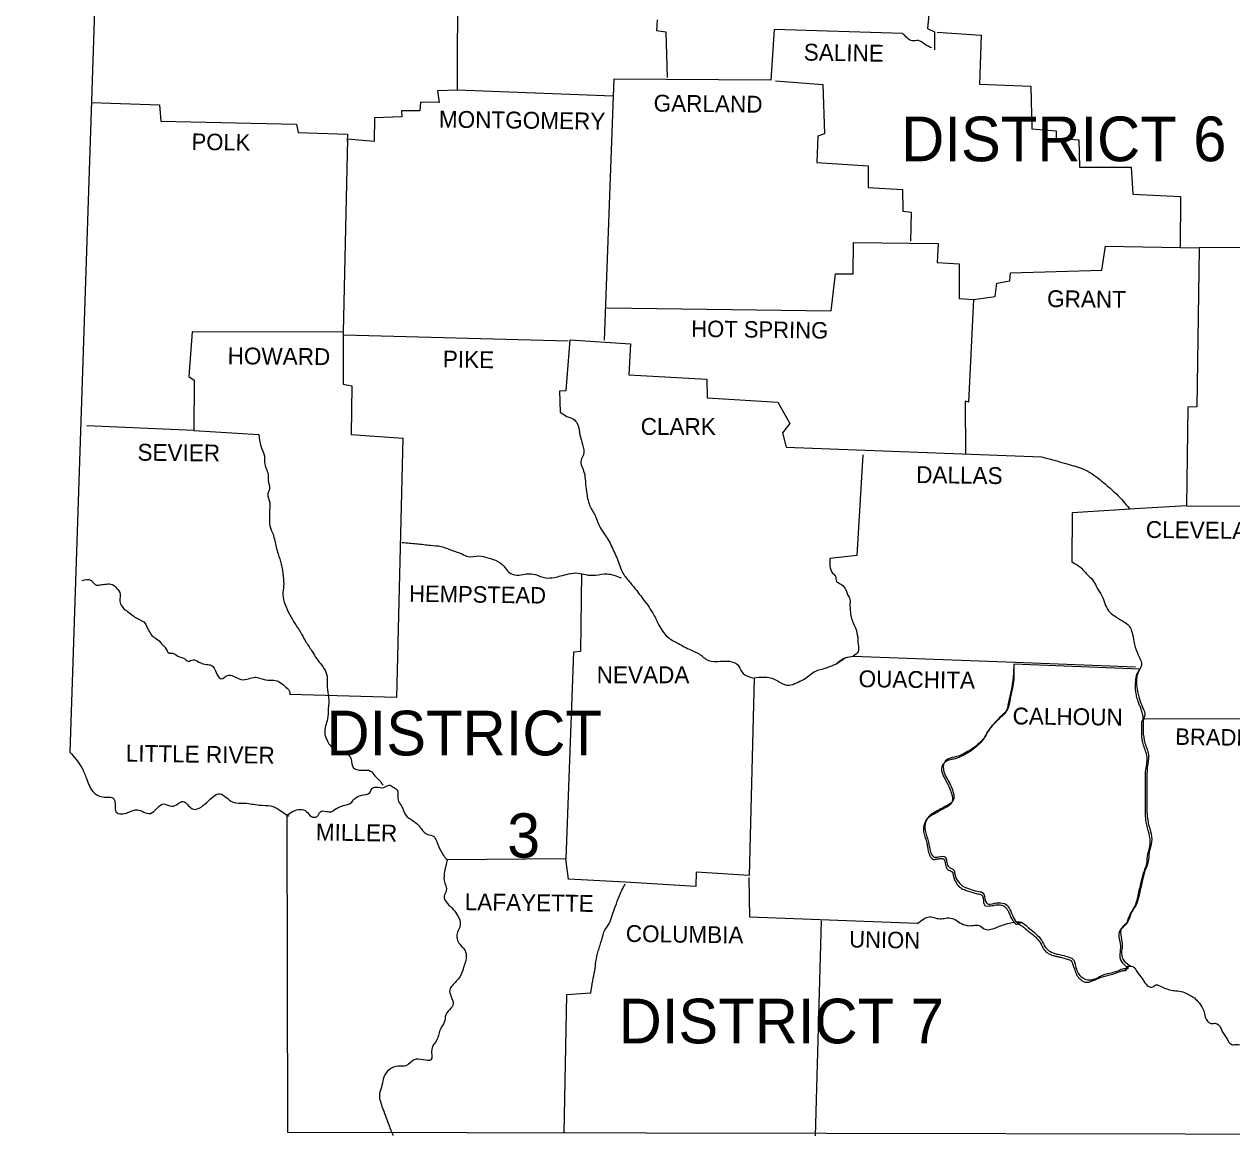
# Model space of a CAD drawing. Extents: x 172 to 3385, y 73 to 2074.
# Drawn here: x 2703.7 to 3005.2, y 1432.6 to 1710.1 of the extents above; entities that cross this region are included whole.
import ezdxf

# ---------------------------------------------------------------- set-up
doc = ezdxf.new("R2010")
doc.units = 0
for name, color, linetype in [('R_Border', 7, 'Continuous'), ('R_Border Prem', 7, 'Continuous'), ('R_Grid', 7, 'Continuous'), ('S_MISC_BOUNDARY', 7, 'Continuous')]:
    doc.layers.add(name, color=color, linetype=linetype)

msp = doc.modelspace()

# ---------------------------------------------------------------- linework, layer by layer
at = {"layer": 'R_Border Prem'}
for points in [[(2703.71, 1956.42), (2723.96, 1793.81), (2715.15, 1528.37)], [(2812.02, 1750.86), (2811.82, 1693.62), (2806.93, 1693.52), (2807.32, 1690.59), (2802.62, 1690.68), (2802.53, 1688.53), (2797.93, 1688.53), (2798.03, 1686.97), (2791.18, 1686.77), (2791.08, 1680.8), (2784.43, 1681.39), (2783.35, 1633.25), (2745.68, 1633.35), (2744.8, 1622.19), (2746.17, 1621.22), (2746.07, 1608.69), (2719.36, 1609.87)], [(2961.91, 1722.77), (2954.86, 1723.56), (2955.16, 1720.92), (2942.34, 1720.43), (2941.95, 1716.61), (2929.91, 1715.93), (2929.23, 1709.08), (2930.99, 1708.2), (2930.99, 1703.7)], [(2861.72, 1711.23), (2861.62, 1708.59), (2863.87, 1708.2), (2864.26, 1696.85)], [(2922.97, 1707.81), (2890.97, 1708.78), (2890.09, 1696.16), (2850.96, 1696.36), (2850.76, 1692.15)], [(2931.68, 1708.1), (2942.63, 1707.41), (2942.24, 1695.18), (2955.06, 1694.69), (2955.26, 1684.03), (2961.32, 1683.54), (2961.32, 1681.68), (2967, 1681.29), (2967.19, 1674.44), (2980.11, 1674.44), (2980.5, 1667.69), (2992.44, 1667.1), (2992.34, 1654.38)], [(2891.27, 1695.97), (2903.11, 1695.09), (2903.5, 1682.76), (2901.83, 1682.17), (2901.64, 1675.62), (2914.46, 1674.74), (2914.46, 1669.35), (2922.97, 1668.86), (2923.07, 1663.48), (2925.12, 1663.19), (2925.02, 1655.95)], [(2850.76, 1692.15), (2811.82, 1693.62)], [(2850.76, 1692.15), (2848.51, 1631.2)], [(2720.54, 1690.59), (2737.46, 1690), (2737.85, 1685.89), (2771.71, 1685.2), (2772.1, 1683.05), (2784.43, 1682.66), (2784.33, 1680.8)], [(3109.06, 1665.64), (3072.08, 1666.61), (3071.88, 1654.58), (2997.03, 1654.29)], [(2849.2, 1639.32), (2905.16, 1638.53), (2906.24, 1647.83), (2910.64, 1647.83), (2910.74, 1655.66), (2931.87, 1655.36), (2931.68, 1650.67), (2937.16, 1650.27), (2937.16, 1641.66), (2940.68, 1641.37)], [(2940.68, 1641.37), (2946.16, 1642.15), (2946.55, 1645.48), (2949.78, 1646.07), (2949.97, 1648.02), (2972.77, 1648.71), (2973.65, 1654.68), (2997.03, 1654.29)], [(2997.03, 1654.09), (2996.45, 1614.56), (2994.2, 1614.47), (2993.9, 1589.91)], [(2940.68, 1641.37), (2939.5, 1615.74), (2938.62, 1616.03), (2938.72, 1602.72)], [(2783.35, 1633.25), (2783.35, 1620.24), (2785.5, 1619.85), (2785.31, 1607.71), (2798.22, 1606.74), (2796.66, 1542.06), (2770.04, 1542.75)], [(2783.55, 1632.57), (2839.51, 1631.1)], [(2837.65, 1613.19), (2837.46, 1618.57), (2839.02, 1618.67), (2840, 1631.29), (2855.07, 1630.32), (2854.68, 1622.59), (2874.15, 1621.51), (2874.24, 1616.81), (2891.85, 1615.74), (2894.89, 1610.45), (2893.03, 1608.11), (2893.91, 1604.49), (2957.7, 1602.14)], [(2746.07, 1608.69), (2762.31, 1607.71)], [(2913.09, 1602.63), (2911.62, 1577.48), (2904.87, 1576.7)], [(2979.81, 1589.03), (2965.33, 1588.15), (2965.24, 1575.92)], [(2993.9, 1589.91), (2979.62, 1589.03)], [(2993.9, 1589.91), (3028.54, 1589.71)], [(2842.84, 1572.98), (2842.64, 1553.51), (2840.88, 1553.31), (2838.92, 1501.75)], [(2910.64, 1552.34), (2951.15, 1550.87), (2981.18, 1549.69)], [(2885.98, 1546.86), (2884.71, 1497.55), (2871.5, 1498.43), (2871.41, 1494.81), (2853.79, 1495.88)], [(2983.14, 1536.68), (3027.36, 1536.78)], [(2769.26, 1512.61), (2769.46, 1433.46), (3128.04, 1432.87)], [(2853.79, 1495.88), (2839.61, 1496.67), (2838.92, 1501.75), (2809.28, 1501.46)], [(2926.69, 1485.61), (2884.91, 1487.17), (2884.71, 1497.06)], [(2902.72, 1486.29), (2901.15, 1432.58)], [(2845.18, 1468.19), (2839.12, 1467.8), (2838.43, 1433.36)]]:
    msp.add_lwpolyline(points, dxfattribs=at)
for points in [[(2930.31, 1704.19), (2928.45, 1705.16), (2926.98, 1706.04), (2925.41, 1705.95), (2924.14, 1706.73), (2922.97, 1707.81)], [(2837.65, 1613.19), (2839.22, 1612.21), (2841.08, 1611.33), (2842.05, 1609.87), (2842.45, 1607.62), (2843.13, 1605.17), (2843.33, 1602.63), (2842.74, 1601.26), (2843.52, 1598.13), (2843.82, 1595.97), (2844.11, 1593.43), (2844.89, 1590.01), (2846.16, 1587.66), (2847.34, 1584.82), (2849.29, 1581.79), (2850.96, 1578.46), (2851.74, 1576.7), (2853.21, 1573.08), (2855.07, 1570.63), (2858, 1566.91), (2860.64, 1563.1), (2862.11, 1560.26), (2864.36, 1557.13), (2866.91, 1555.57), (2870.13, 1553.9), (2872.19, 1552.92), (2874.54, 1551.26), (2877.57, 1551.06), (2879.82, 1551.06), (2881.88, 1550.18), (2882.85, 1548.42), (2884.61, 1547.25), (2885.98, 1546.86)], [(2762.31, 1607.71), (2762.8, 1604.78), (2763.68, 1602.24), (2763.78, 1600.28), (2764.66, 1597.34), (2764.66, 1596.27), (2764.96, 1594.11), (2764.56, 1592.94), (2765.05, 1590.59), (2764.96, 1588.83), (2764.96, 1587.36), (2765.05, 1584.92), (2765.84, 1582.76), (2766.62, 1579.54), (2767.11, 1577.87), (2767.89, 1575.33), (2768.38, 1572.2), (2768.48, 1569.85), (2768.28, 1567.7), (2768.87, 1565.25), (2769.95, 1562.81), (2771.32, 1560.46), (2772.98, 1557.82), (2774.15, 1555.76), (2775.62, 1553.51), (2776.79, 1551.65), (2778.56, 1549.3), (2779.34, 1547.35), (2779.34, 1544.61), (2779.73, 1542.06), (2779.63, 1539.23), (2779.44, 1536.68), (2778.75, 1533.16), (2779.24, 1531.5), (2781.1, 1529.05), (2782.27, 1528.37), (2784.33, 1527.97), (2785.31, 1526.6), (2785.89, 1524.55), (2787.95, 1523.86), (2790.2, 1523.67), (2791.27, 1522.49), (2792.74, 1520.93), (2793.23, 1520.15)], [(2957.7, 1602.14), (2965.33, 1599.98), (2969.25, 1598.52), (2973.16, 1595.68), (2976.39, 1592.84), (2979.62, 1589.22)], [(2798.03, 1580.71), (2801.74, 1580.42), (2805.17, 1580.03), (2807.81, 1579.73), (2810.55, 1578.75), (2813, 1577.87), (2814.56, 1577.19), (2817.2, 1577.38), (2819.45, 1576.89), (2822, 1576.01), (2823.86, 1574.35), (2825.03, 1573.08), (2827.28, 1572.59), (2829.14, 1572.88), (2831.39, 1572.69), (2833.93, 1571.9), (2835.99, 1572), (2837.65, 1572.39), (2839.61, 1572.88), (2842.05, 1573.08), (2843.91, 1572.69), (2846.36, 1572.59), (2849.2, 1572.88), (2852.72, 1571.9)], [(2904.87, 1576.7), (2904.87, 1574.84), (2905.55, 1573.08), (2906.24, 1572.3), (2906.53, 1571.02), (2907.41, 1570.44), (2908.68, 1569.26), (2909.37, 1567.6), (2909.86, 1566.52), (2909.86, 1565.15), (2909.96, 1563.78), (2910.15, 1562.12), (2911.33, 1559.19), (2911.62, 1558.01), (2911.81, 1557.03), (2911.91, 1555.37), (2911.91, 1553.41), (2910.64, 1552.34)], [(2965.24, 1575.92), (2967.49, 1574.45), (2969.34, 1572.49), (2970.71, 1571.02), (2971.59, 1569.36), (2972.77, 1567.4), (2974.43, 1563.69), (2975.9, 1562.41), (2977.95, 1561.14), (2979.23, 1560.26), (2980.5, 1557.42), (2981.09, 1554.59), (2982.16, 1552.04), (2982.65, 1550.09), (2981.77, 1548.13), (2981.57, 1544.22), (2982.16, 1541.57), (2982.94, 1539.62), (2983.43, 1537.37), (2983.14, 1536.68)], [(2718.19, 1571.22), (2720.34, 1571.32), (2721.81, 1570.05), (2722.69, 1570.14), (2724.25, 1570.34), (2725.72, 1570.24), (2726.8, 1569.36), (2727.68, 1567.8), (2727.58, 1566.33), (2727.68, 1565.74), (2728.36, 1564.47), (2729.54, 1563.49), (2730.81, 1562.51), (2731.98, 1561.73), (2733.94, 1560.46), (2734.14, 1560.07), (2734.92, 1558.5), (2735.9, 1557.23), (2737.07, 1556.45), (2738.34, 1555.08), (2738.93, 1554.49), (2739.91, 1553.12), (2740.98, 1553.02), (2742.45, 1552.14), (2743.53, 1551.85), (2744.7, 1551.06), (2745.88, 1551.46), (2747.34, 1550.87), (2749.3, 1550.28), (2750.38, 1550.09), (2751.65, 1548.23), (2752.92, 1546.66), (2754.49, 1547.54), (2757.42, 1546.66), (2759.28, 1546.56), (2760.94, 1547.05), (2762.22, 1546.96), (2764.56, 1546.37), (2766.03, 1546.37), (2767.6, 1545.78), (2769.06, 1544.61), (2770.04, 1543.34), (2770.04, 1542.75)], [(2908.78, 1551.95), (2906.24, 1550.28), (2904.28, 1549.5), (2902.81, 1549.01), (2901.44, 1548.62), (2899.68, 1547.44), (2898.31, 1546.47), (2896.45, 1545.59), (2894.69, 1545), (2892.54, 1545.68), (2891.37, 1546.37), (2890.09, 1546.86), (2885.98, 1546.86)], [(2906.24, 1550.28), (2908.78, 1551.95), (2910.64, 1552.34)], [(2950.75, 1549.69), (2950.56, 1544.8), (2949.87, 1541.77), (2949.19, 1539.03), (2947.72, 1537.46), (2946.16, 1535.9), (2944.69, 1534.14), (2943.42, 1531.99), (2942.14, 1530.62), (2940.48, 1529.25), (2938.82, 1528.27), (2936.96, 1527.39), (2934.9, 1526.9), (2933.44, 1525.82), (2933.34, 1523.47), (2935, 1520.15), (2935.59, 1518.58), (2935.79, 1516.72), (2935.1, 1515.65), (2933.53, 1514.77), (2931.68, 1513.69), (2930.01, 1512.71), (2928.84, 1511.05), (2928.64, 1508.8), (2929.43, 1506.16), (2929.72, 1504.59), (2930.99, 1502.14), (2931.97, 1502.24), (2933.73, 1502.14), (2933.93, 1501.65), (2934.02, 1501.17), (2934.42, 1499.89), (2935.88, 1498.82), (2936.08, 1497.84), (2936.96, 1495.98), (2938.43, 1494.71), (2939.5, 1494.32), (2941.75, 1493.63), (2942.93, 1493.34), (2944.2, 1490.5), (2945.77, 1490.6), (2946.94, 1490.79), (2948.9, 1490.31), (2949.78, 1489.13), (2950.66, 1487.17), (2951.83, 1485.8), (2952.61, 1485.8)], [(2983.14, 1536.68), (2983.53, 1530.62), (2984.41, 1527.68), (2984.12, 1524.55), (2984.02, 1521.52), (2984.02, 1518.78), (2984.02, 1516.14), (2984.02, 1513.4), (2984.22, 1511.44), (2984.9, 1508.6), (2985.19, 1505.96), (2984.61, 1503.42), (2984.31, 1501.07), (2983.53, 1498.72), (2982.85, 1496.08), (2982.06, 1492.65), (2981.38, 1490.4), (2980.01, 1488.06), (2979.13, 1485.9), (2977.76, 1484.53), (2977.56, 1482.18), (2977.86, 1480.03), (2977.66, 1478.08), (2978.35, 1476.22), (2980.11, 1474.94)], [(2715.15, 1528.37), (2717.99, 1524.65), (2719.17, 1522.01), (2720.83, 1518.58), (2723.28, 1517.21), (2726.11, 1516.72), (2726.7, 1513.4), (2729.63, 1513.3), (2731.98, 1513.98), (2735.21, 1513.1), (2738.64, 1515.45), (2740.59, 1514.86), (2743.43, 1516.04), (2745.58, 1514.28), (2749.3, 1515.84), (2752.63, 1517.99), (2755.76, 1515.94), (2758.79, 1515.65), (2762.41, 1515.16), (2765.25, 1514.96), (2767.79, 1513.69), (2769.65, 1512.42), (2769.26, 1512.61)], [(2769.26, 1512.61), (2772.68, 1514.08), (2774.15, 1513.59), (2775.42, 1512.32), (2776.89, 1512.32), (2777.67, 1513.49), (2779.14, 1513.59), (2780.32, 1513.49), (2781.59, 1514.28), (2782.66, 1514.77), (2784.13, 1515.25), (2785.21, 1515.65), (2786.19, 1516.72), (2787.95, 1517.6), (2790, 1518.29), (2790.59, 1519.27), (2791.57, 1519.66), (2793.52, 1519.56), (2794.8, 1520.15), (2795.87, 1519.66), (2796.85, 1518.97), (2797.05, 1516.43), (2797.83, 1515.06), (2799, 1512.61), (2800.67, 1511.34), (2802.23, 1510.07), (2802.82, 1509.29), (2804.48, 1507.82), (2805.95, 1507.33), (2806.64, 1506.25), (2807.71, 1503.71), (2809.28, 1501.46)], [(2809.28, 1501.46), (2808.69, 1498.62), (2808.59, 1496.37), (2809.08, 1493.73), (2808.59, 1492.46), (2809.38, 1490.6), (2810.84, 1489.13), (2811.92, 1487.57), (2812.6, 1485.32), (2811.72, 1482.77), (2812.7, 1480.13), (2813.58, 1479.15), (2814.07, 1477.59), (2813.39, 1474.55), (2812.51, 1472.3), (2810.55, 1470.05), (2809.96, 1468.98), (2810.26, 1467.51), (2810.74, 1465.16), (2810.26, 1464.48), (2808.98, 1462.81), (2808.59, 1460.95), (2807.71, 1459.39), (2806.73, 1456.55), (2805.46, 1454.2), (2805.27, 1451.56), (2803.31, 1451.56), (2801.06, 1451.56), (2799, 1450.09), (2797.15, 1450), (2794.89, 1449.11), (2793.52, 1447.26), (2793.04, 1445.2), (2792.45, 1443.24), (2793.04, 1439.92), (2793.92, 1437.57), (2794.6, 1435.71), (2795.78, 1432.68)], [(2845.18, 1468.19), (2845.67, 1471.32), (2846.16, 1473.77), (2846.46, 1476.12), (2847.04, 1478.76), (2847.92, 1481.6), (2848.71, 1483.95), (2849.78, 1485.61), (2850.47, 1487.57), (2851.35, 1489.91), (2852.23, 1492.36), (2853.79, 1495.49)], [(2926.69, 1485.61), (2928.25, 1486.69), (2929.72, 1487.27), (2931.19, 1486.98), (2932.75, 1486.78), (2934.12, 1486.98), (2935.88, 1486.69), (2937.35, 1485.8), (2939.01, 1485.12), (2940.68, 1485.12), (2942.14, 1485.12), (2943.42, 1484.24), (2945.77, 1484.34), (2947.72, 1485.12), (2949.68, 1485.71), (2952.32, 1486), (2954.67, 1484.34), (2956.33, 1482.97), (2957.7, 1481.4), (2958.68, 1479.64), (2959.76, 1478.66), (2961.52, 1477.98), (2962.89, 1477.68), (2964.55, 1477.19), (2965.43, 1476.8), (2966.21, 1474.94), (2967.49, 1472.4), (2969.93, 1471.52), (2972.96, 1472.69), (2975.41, 1473.38), (2977.17, 1473.97), (2978.25, 1474.36), (2979.23, 1474.46), (2978.93, 1474.65), (2980.11, 1474.94), (2981.18, 1474.16), (2981.87, 1473.09), (2983.04, 1471.52), (2984.12, 1470.15), (2985.19, 1469.66), (2986.27, 1470.25), (2987.74, 1469.76), (2989.01, 1469.27), (2990.48, 1468.88), (2991.75, 1468.78), (2993.41, 1468.39), (2994.69, 1467.7), (2995.86, 1467.02), (2997.03, 1465.75), (2998.21, 1463.79), (2998.6, 1462.23), (2999.97, 1460.66), (3001.24, 1460.66), (3003.1, 1458.12), (3003.78, 1457.14), (3005.25, 1455.38), (3006.33, 1455.38), (3008.38, 1454.98)]]:
    msp.add_spline(points, degree=3, dxfattribs=at)
at = {"layer": 'S_MISC_BOUNDARY'}
msp.add_line((2982.21, 1549.11), (2950.79, 1550.34), dxfattribs=at)
for points in [[(2950.79, 1550.34), (2950.63, 1547.29), (2950.46, 1545.78), (2950.2, 1544.27), (2949.52, 1541.24), (2949.26, 1539.85), (2949.09, 1539.16), (2948.98, 1538.83), (2948.91, 1538.66), (2948.83, 1538.5), (2948.54, 1538.05), (2948.17, 1537.66), (2947.37, 1536.93), (2946.58, 1536.15), (2945.8, 1535.37), (2944.33, 1533.61), (2943.99, 1533.08), (2943.7, 1532.53), (2943.4, 1531.98), (2943.06, 1531.45), (2941.91, 1530.19)], [(2982.78, 1536.15), (2982.91, 1536.31), (2983, 1536.48), (2983.08, 1536.83), (2983.06, 1537.11), (2983.03, 1537.4), (2982.92, 1537.96), (2982.77, 1538.53), (2982.59, 1539.08), (2982.4, 1539.58), (2982.19, 1540.06), (2981.99, 1540.54), (2981.81, 1541.04), (2981.45, 1542.35), (2981.22, 1543.68), (2981.15, 1544.66), (2981.17, 1545.64), (2981.27, 1546.63), (2981.34, 1547.12), (2981.42, 1547.6), (2981.55, 1547.99), (2981.77, 1548.37), (2982.01, 1548.74), (2982.21, 1549.11)], [(2979.39, 1474.41), (2977.99, 1475.68), (2977.31, 1477.54), (2977.5, 1479.5), (2977.21, 1481.65), (2977.4, 1484), (2978.77, 1485.37), (2979.65, 1487.52), (2981.02, 1489.87), (2981.71, 1492.12), (2982.49, 1495.55), (2983.18, 1498.19), (2983.96, 1500.53), (2984.25, 1502.88), (2984.84, 1505.43), (2984.55, 1508.07), (2983.86, 1510.91), (2983.67, 1512.86), (2983.67, 1515.6), (2983.67, 1518.24), (2983.67, 1520.98), (2983.76, 1524.02), (2984.06, 1527.15), (2983.18, 1530.08), (2982.78, 1536.15)], [(2941.91, 1530.19), (2941.79, 1530.08), (2940.13, 1528.71), (2938.46, 1527.73), (2936.6, 1526.85), (2936.11, 1526.7), (2935.59, 1526.6), (2935.06, 1526.51), (2934.55, 1526.36), (2933.74, 1525.95), (2933.39, 1525.66), (2933.23, 1525.48), (2933.08, 1525.29), (2932.82, 1524.72), (2932.74, 1524.11), (2932.98, 1522.94), (2933.38, 1522.11), (2933.82, 1521.29), (2934.26, 1520.46), (2934.65, 1519.61), (2935.23, 1518.05), (2935.36, 1517.59), (2935.45, 1517.12), (2935.47, 1516.65), (2935.43, 1516.19), (2934.75, 1515.11), (2933.3, 1514.3)], [(2933.3, 1514.3), (2933.18, 1514.23), (2931.32, 1513.16), (2929.66, 1512.18), (2929.26, 1511.86), (2928.94, 1511.46), (2928.69, 1511), (2928.48, 1510.51), (2928.22, 1509.39), (2928.29, 1508.26), (2928.47, 1507.6), (2928.68, 1506.94), (2928.89, 1506.29), (2929.07, 1505.62), (2929.22, 1504.84), (2929.28, 1504.45), (2929.36, 1504.06), (2929.52, 1503.36), (2929.74, 1502.67), (2930.08, 1502.06), (2930.33, 1501.81), (2930.47, 1501.71), (2930.64, 1501.61), (2930.88, 1501.56), (2931.12, 1501.6), (2931.37, 1501.67), (2931.61, 1501.71), (2931.83, 1501.72), (2932.06, 1501.76), (2932.5, 1501.82), (2932.94, 1501.8), (2933.16, 1501.74), (2933.27, 1501.68), (2933.38, 1501.61), (2933.52, 1501.38), (2933.57, 1501.12), (2933.67, 1500.63), (2934.06, 1499.36), (2934.35, 1499.03), (2934.79, 1498.82), (2935.23, 1498.61), (2935.53, 1498.28), (2935.57, 1498.18)], [(2935.57, 1498.18), (2935.6, 1498.05), (2935.63, 1497.8), (2935.66, 1497.55), (2935.72, 1497.31), (2936.1, 1496.36), (2936.6, 1495.45), (2936.92, 1495.05), (2937.26, 1494.7), (2938.07, 1494.18), (2939.15, 1493.78), (2941.4, 1493.1), (2942.57, 1492.81), (2942.74, 1492.73), (2943.05, 1492.25), (2943.2, 1491.31), (2943.35, 1490.4), (2943.54, 1490.1), (2943.84, 1489.97), (2944.63, 1489.98), (2945.41, 1490.07), (2946.58, 1490.26), (2947.57, 1490.21), (2948.06, 1490.05), (2948.3, 1489.93), (2948.54, 1489.77), (2949.06, 1489.22), (2949.42, 1488.6), (2949.66, 1488.11), (2949.86, 1487.62), (2950.06, 1487.13), (2950.3, 1486.64), (2951.26, 1485.45)], [(2951.26, 1485.45), (2951.43, 1485.43), (2951.62, 1485.47), (2951.8, 1485.5), (2951.97, 1485.47), (2952.12, 1485.38), (2952.28, 1485.3), (2952.59, 1485.12), (2952.89, 1484.93), (2953.18, 1484.71), (2954.31, 1483.8), (2955.16, 1483.13), (2955.98, 1482.43), (2956.7, 1481.69), (2957.03, 1481.29), (2957.35, 1480.87), (2957.61, 1480.45), (2957.84, 1479.99), (2958.06, 1479.54), (2958.32, 1479.11), (2959.4, 1478.13), (2959.83, 1477.91), (2960.13, 1477.78)], [(2960.13, 1477.78), (2960.26, 1477.73), (2961.16, 1477.44), (2961.5, 1477.37), (2961.85, 1477.3), (2962.19, 1477.23), (2962.53, 1477.15), (2964.2, 1476.66), (2964.67, 1476.53), (2964.89, 1476.43), (2965.08, 1476.27), (2965.35, 1475.83), (2965.53, 1475.36), (2965.68, 1474.88), (2965.86, 1474.41), (2965.99, 1474.09), (2966.11, 1473.77), (2966.33, 1473.13), (2966.64, 1472.49), (2966.85, 1472.18), (2966.98, 1472.02), (2967.13, 1471.87), (2967.72, 1471.38), (2968.34, 1471.06), (2968.88, 1470.93)], [(2968.88, 1470.93), (2968.96, 1470.92), (2969.58, 1470.99), (2970.33, 1471.25), (2971.09, 1471.57), (2971.85, 1471.89), (2972.61, 1472.16), (2973.22, 1472.34), (2973.83, 1472.5), (2974.45, 1472.67), (2975.06, 1472.85), (2976.82, 1473.43), (2977.89, 1473.82), (2978.13, 1473.87), (2978.38, 1473.88), (2978.63, 1473.88), (2978.87, 1473.92), (2978.89, 1473.94), (2978.86, 1473.96), (2978.73, 1474.01), (2978.6, 1474.07), (2978.57, 1474.1), (2978.58, 1474.12), (2978.85, 1474.25), (2979.16, 1474.36), (2979.39, 1474.41)]]:
    msp.add_spline(points, degree=3, dxfattribs=at)

# ---------------------------------------------------------------- texts
at = {"layer": 'R_Border'}
for s, height, rotation, p in [('SALINE', 4.207, 359.1491, (2898.31, 1701.05)), ('GARLAND', 4.207, 359.3658, (2860.84, 1688.33)), ('MONTGOMERY', 4.207, 359.2944, (2807.22, 1684.32)), ('POLK', 4.108, 359.2152, (2745.49, 1678.75)), ('GRANT', 4.207, 359.4032, (2959.07, 1639.51)), ('HOT SPRING', 4.109, 359.2216, (2870.23, 1632.08)), ('HOWARD', 4.207, 359.5145, (2754.49, 1625.23)), ('PIKE', 4.206, 359.0452, (2808.2, 1624.44)), ('SEVIER', 4.207, 359.4271, (2731.98, 1601.16)), ('DALLAS', 4.206, 359.2462, (2926.39, 1595.58)), ('CLEVELAND', 4.207, 359.3377, (2983.73, 1581.88)), ('HEMPSTEAD', 4.108, 359.1885, (2799.79, 1565.94)), ('OUACHITA', 4.207, 359.2043, (2912.01, 1544.61)), ('CALHOUN', 4.207, 359.3634, (2950.46, 1535.31)), ('BRADLEY', 4.108, 359.1449, (2991.07, 1530.22)), ('LITTLE RIVER', 4.2073, 359.1697, (2729.05, 1526.02)), ('MILLER', 4.206, 359.1319, (2776.5, 1506.35)), ('LAFAYETTE', 4.206, 359.1839, (2813.68, 1488.94)), ('COLUMBIA', 4.206, 359.2125, (2853.89, 1481.01)), ('UNION', 4.109, 358.9584, (2909.66, 1479.64))]:
    msp.add_text(s, height=height, rotation=rotation, dxfattribs=at).set_placement(p)
for s, p in [('CLARK', (2857.63, 1607.59)), ('NEVADA', (2846.65, 1545.59))]:
    msp.add_text(s, height=4.207, dxfattribs=at).set_placement(p)
at = {"layer": 'R_Grid'}
for s, height, p in [('DISTRICT 6', 11.154, (2922.67, 1675.91)), ('DISTRICT', 11.154, (2779.19, 1527.57)), ('3', 11.06, (2824.3, 1502.04)), ('DISTRICT 7', 11.154, (2852.13, 1455.67))]:
    msp.add_text(s, height=height, dxfattribs=at).set_placement(p)

doc.saveas('drawing.dxf')
